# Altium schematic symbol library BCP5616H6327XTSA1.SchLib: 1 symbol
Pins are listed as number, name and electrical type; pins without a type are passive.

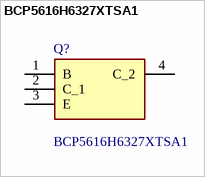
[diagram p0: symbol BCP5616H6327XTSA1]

## BCP5616H6327XTSA1
designator Q?
For AF driver and output stages  High collector current  Low collector-emitter saturation voltage  Complementary types: BCP51...BCP53 (PNP)  Pb-free (RoHS compliant) package  Qualified according AEC Q10; Manufacturer_Name: Infineon; Geometry.Height: 1.8mm
footprint SOT230P700X180-4N
pins: 1 B, 2 C_1, 3 E, 4 C_2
